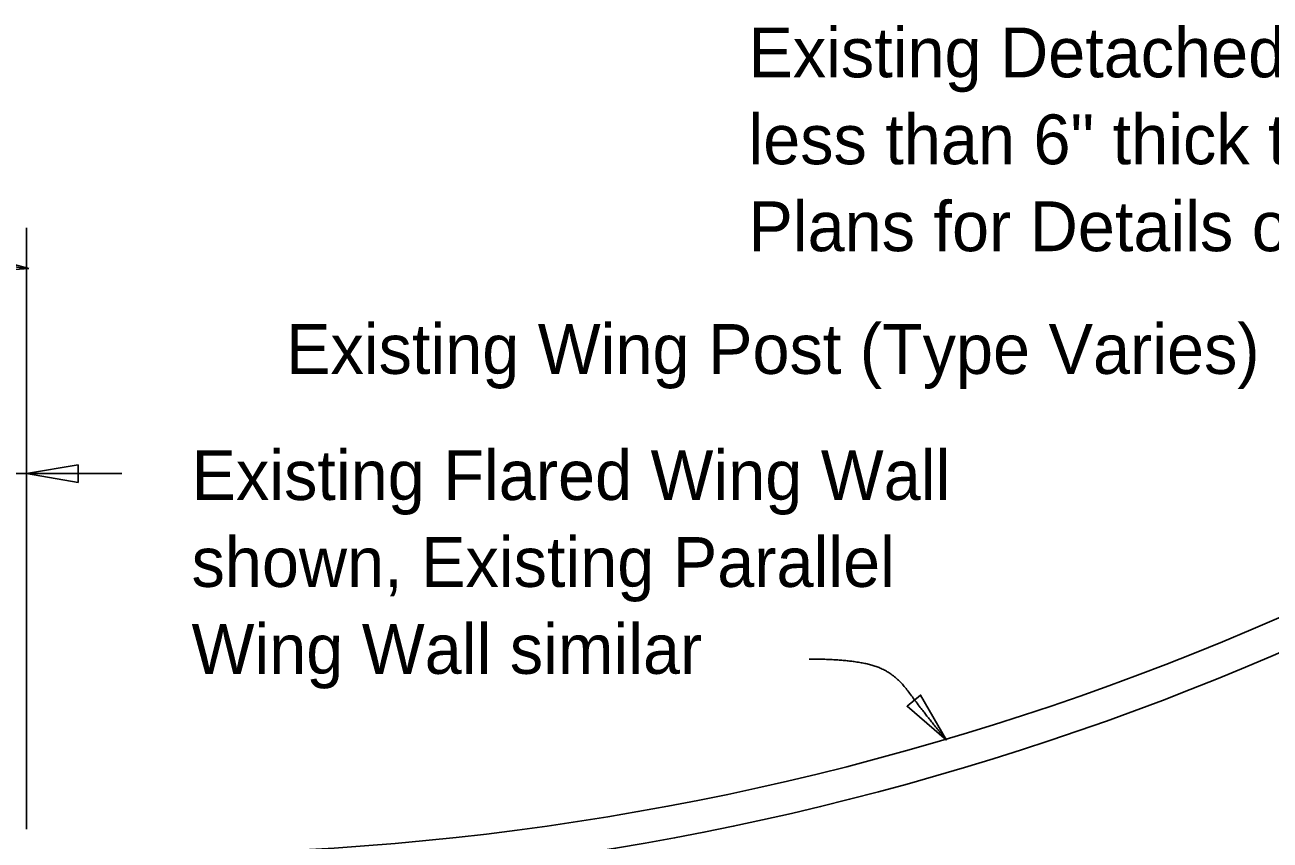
# Model space of a CAD drawing. Extents: x 21526.6 to 21598.7, y 56118.9 to 56155.9.
# Drawn here: x 21554.3 to 21559.34, y 56149.76 to 56153.06 of the extents above; entities that cross this region are included whole.
import ezdxf

# ---------------------------------------------------------------- set-up
doc = ezdxf.new("R2010")
doc.units = 0
for name, color, linetype in [('AdhocPoint_dp', 7, 'Continuous'), ('Border', 7, 'Continuous'), ('PlotBorder_dp', 7, 'Continuous')]:
    doc.layers.add(name, color=color, linetype=linetype)

msp = doc.modelspace()

# ---------------------------------------------------------------- linework, layer by layer
at = {"layer": 'AdhocPoint_dp'}
for radius, start, end in [(11.3394, 267.40102, 307.51098), (11.4702, 267.84731, 306.6471), (12.5106, 267.64448, 307.24718), (12.3856, 268.00648, 306.50279), (12.5523, 272.40859, 307.2387)]:
    msp.add_arc((21554.816, 56161.0472), radius, start, end, dxfattribs=at)
at = {"layer": 'PlotBorder_dp'}
for p, q in [((21554.3043, 56149.8081), (21554.3043, 56152.2434)), ((21554.6897, 56151.2476), (21550.7812, 56151.2476))]:
    msp.add_line(p, q, dxfattribs=at)
for points in [[(21554.3137, 56152.0784), (21554.11, 56152.1343), (21554.103, 56152.0641)], [(21554.3043, 56151.2476), (21554.5126, 56151.2123), (21554.5126, 56151.2828)], [(21558.0282, 56150.1678), (21557.9231, 56150.351), (21557.8686, 56150.3061)]]:
    msp.add_lwpolyline(points, close=True, dxfattribs=at)
for points in [[(21553.1921, 56152.3226), (21553.3769, 56152.316), (21553.6144, 56152.217), (21553.6474, 56152.1576), (21553.9178, 56152.118), (21554.3137, 56152.0784)], [(21557.4723, 56150.4969), (21557.6302, 56150.4969), (21557.8111, 56150.4508), (21557.9361, 56150.2797), (21558.0282, 56150.1678)]]:
    msp.add_open_spline(points, degree=2, dxfattribs=at)

# ---------------------------------------------------------------- texts
at = {"layer": 'Border'}
msp.add_text('Existing Wing Post (Type Varies)', height=0.2016, dxfattribs=at).set_placement((21555.3548, 56151.6515))
at = {"layer": 'PlotBorder_dp'}
for s, p in [('Existing Detached Sidewalk or Integral Sidewalk ', (21557.226, 56152.8524)), ('less than 6" thick to be removed.  See Roadway ', (21557.226, 56152.5004)), ('Plans for Details of Sidewalk replacement.', (21557.226, 56152.1484)), ('Existing Flared Wing Wall ', (21554.9722, 56151.141)), ('shown, Existing Parallel ', (21554.9722, 56150.789)), ('Wing Wall similar', (21554.9722, 56150.437))]:
    msp.add_text(s, height=0.2016, dxfattribs=at).set_placement(p)

doc.saveas('drawing.dxf')
